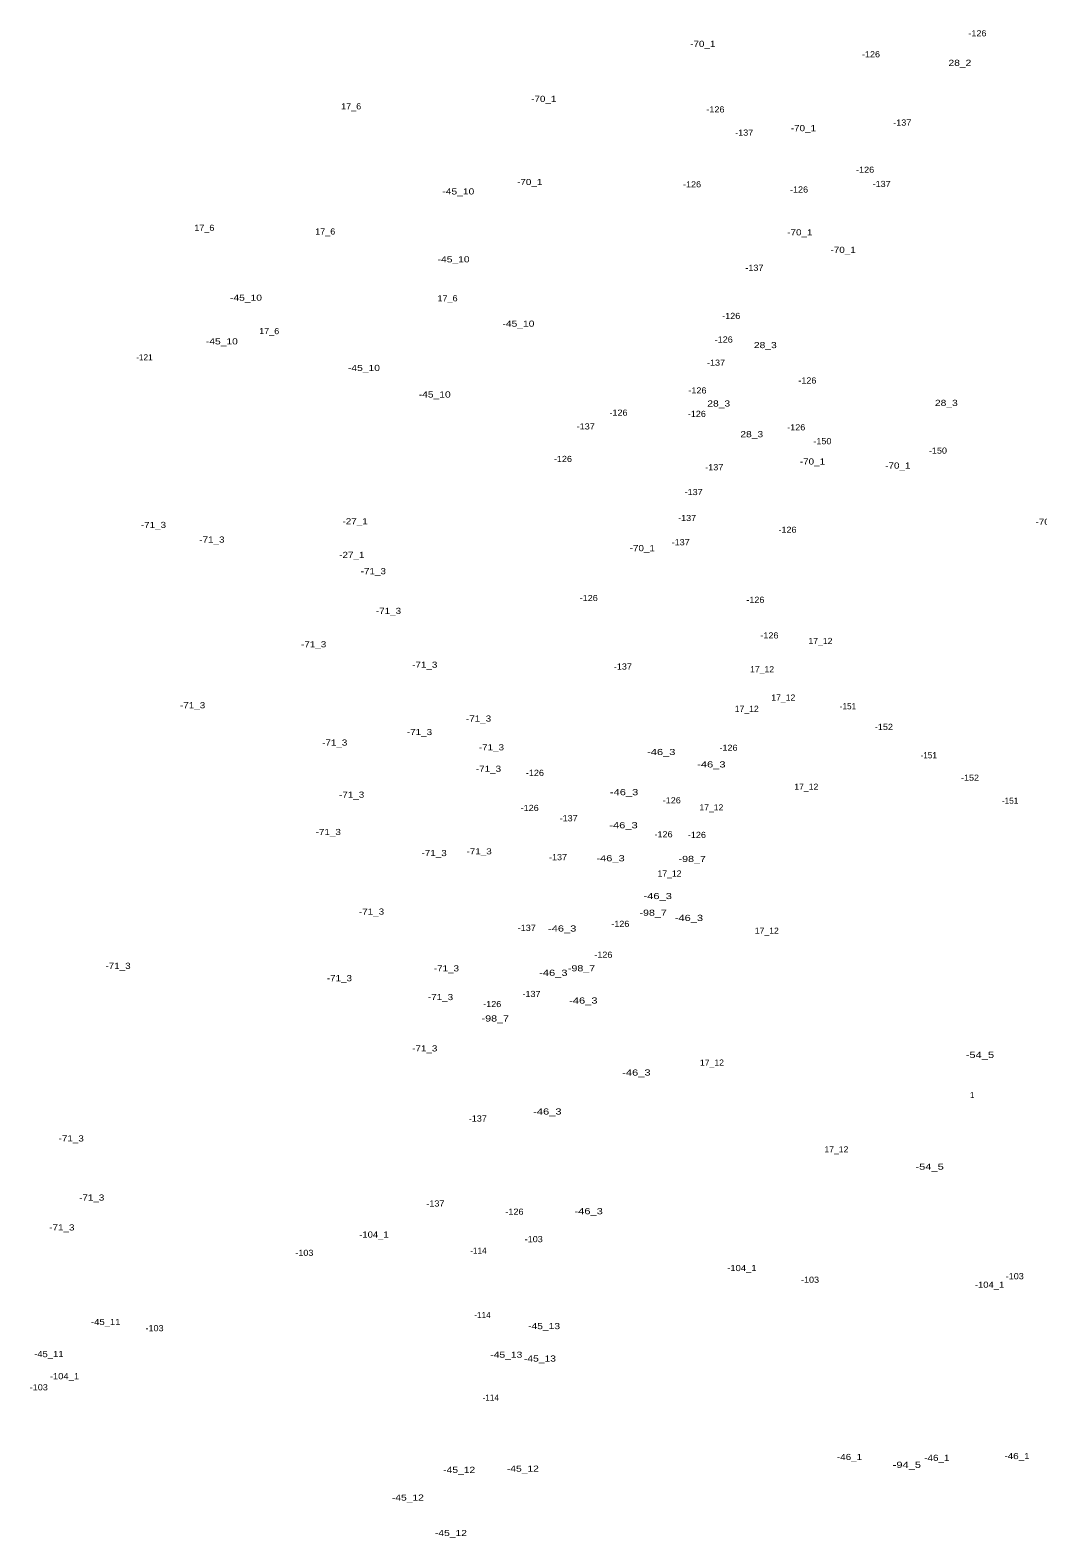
# Model space of a CAD drawing. Extents: x -662996 to -659766, y -998554 to -993949.
# Drawn here: x -662156 to -661500, y -998253 to -997272 of the extents above; entities that cross this region are included whole.
import ezdxf
from ezdxf.enums import TextEntityAlignment as Align

# ---------------------------------------------------------------- set-up
doc = ezdxf.new("R2010")
doc.units = 0
doc.header["$LTSCALE"] = 1.6
doc.layers.add('24', color=7, linetype='Continuous')

msp = doc.modelspace()

# ---------------------------------------------------------------- texts
at = {"layer": '24'}
for s, width, p in [('-126', 1.1, (-661539.28, -997275.58)), ('-70_1', 1.2, (-661718.111, -997282.43)), ('-126', 1.1, (-661608.59, -997289.21)), ('28_2', 1.25, (-661550.68, -997294.78)), ('-70_1', 1.2, (-661821.691, -997318.24)), ('17_6', 1.1, (-661947.12, -997323.09)), ('-126', 1.1, (-661709.89, -997325.1)), ('-70_1', 1.2, (-661652.611, -997337.28)), ('-137', 1.1, (-661588.22, -997333.66)), ('-137', 1.1, (-661691.14, -997340.19)), ('-126', 1.1, (-661612.4, -997364.34)), ('-45_10', 1.25, (-661877.35, -997378.47)), ('-70_1', 1.2, (-661830.831, -997372.33)), ('-126', 1.1, (-661725.12, -997373.86)), ('-126', 1.1, (-661655.43, -997377.21)), ('-137', 1.1, (-661601.66, -997373.61)), ('17_6', 1.1, (-662042.74, -997402.14)), ('17_6', 1.1, (-661964.01, -997404.53)), ('-70_1', 1.2, (-661654.89, -997405.09)), ('-70_1', 1.2, (-661626.711, -997416.52)), ('-45_10', 1.25, (-661880.419, -997422.65)), ('-137', 1.1, (-661684.53, -997428.17)), ('-45_10', 1.25, (-662015.6, -997447.62)), ('17_6', 1.1, (-661884.341, -997448.02)), ('-45_10', 1.25, (-661838.179, -997464.52)), ('-126', 1.1, (-661699.6, -997459.49)), ('-45_10', 1.25, (-662031.34, -997476.05)), ('17_6', 1.1, (-662000.49, -997469.36)), ('-126', 1.1, (-661704.48, -997474.83)), ('28_3', 1.25, (-661677.4, -997478.46)), ('-45_10', 1.25, (-661938.79, -997493.33)), ('-137', 1.1, (-661709.5, -997489.91)), ('-126', 1.1, (-661650.02, -997501.5)), ('-45_10', 1.25, (-661892.709, -997510.62)), ('-126', 1.1, (-661721.61, -997507.98)), ('-126', 1.1, (-661773.02, -997522.45)), ('-126', 1.1, (-661721.99, -997523.22)), ('28_3', 1.25, (-661707.74, -997516.49)), ('28_3', 1.25, (-661559.51, -997516.1)), ('-137', 1.1, (-661794.36, -997531.4)), ('-126', 1.1, (-661657.25, -997531.98)), ('28_3', 1.25, (-661686.23, -997536.46)), ('-150', 1.1, (-661640.24, -997541)), ('-126', 1.1, (-661809.2, -997552.55)), ('-70_1', 1.2, (-661646.701, -997554.22)), ('-150', 1.1, (-661564.981, -997547.14)), ('-137', 1.1, (-661710.65, -997557.96)), ('-70_1', 1.2, (-661591.101, -997556.88)), ('-137', 1.1, (-661724.09, -997574.1)), ('-27_1', 1.2, (-661944.57, -997593.13)), ('-137', 1.1, (-661728.31, -997591)), ('-70_1', 1.2, (-661493.231, -997593.46)), ('-71_3', 1.2, (-662075.88, -997595.52)), ('-126', 1.1, (-661662.97, -997598.64)), ('-71_3', 1.2, (-662037.8, -997605.04)), ('-70_1', 1.2, (-661757.52, -997610.6)), ('-137', 1.1, (-661732.53, -997606.75)), ('-27_1', 1.2, (-661946.68, -997615.02)), ('-71_3', 1.2, (-661932.7, -997625.59)), ('-126', 1.1, (-661792.41, -997643.08)), ('-71_3', 1.2, (-661922.8, -997651.46)), ('-126', 1.1, (-661683.87, -997644.23)), ('-126', 1.1, (-661674.73, -997667.41)), ('17_12', 1.05, (-661641.49, -997671.01)), ('-71_3', 1.2, (-661971.54, -997673.17)), ('-71_3', 1.2, (-661899.19, -997686.48)), ('-137', 1.1, (-661770.17, -997687.64)), ('17_12', 1.05, (-661679.5, -997689.42)), ('17_12', 1.05, (-661665.68, -997707.86)), ('-71_3', 1.2, (-662050.37, -997712.85)), ('-71_3', 1.2, (-661864.15, -997721.53)), ('17_12', 1.05, (-661689.49, -997715.16)), ('-71_3', 1.2, (-661902.61, -997730.29)), ('-152', 1.1, (-661600.16, -997726.95)), ('-71_3', 1.2, (-661957.83, -997737.15)), ('-71_3', 1.2, (-661855.77, -997740.2)), ('-126', 1.1, (-661701.39, -997740.52)), ('-46_3', 1.35, (-661745.18, -997743.28)), ('-46_3', 1.35, (-661712.54, -997751.35)), ('-71_3', 1.2, (-661857.68, -997754.18)), ('-126', 1.1, (-661827.44, -997756.83)), ('-152', 1.1, (-661544.101, -997759.99)), ('-71_3', 1.2, (-661946.79, -997771.05)), ('-46_3', 1.35, (-661769.37, -997769.4)), ('17_12', 1.05, (-661650.7, -997765.89)), ('-126', 1.1, (-661830.87, -997779.69)), ('-126', 1.1, (-661738.33, -997774.74)), ('17_12', 1.05, (-661712.53, -997779.31)), ('-137', 1.1, (-661805.5, -997786.37)), ('-71_3', 1.2, (-661962.02, -997795.33)), ('-46_3', 1.35, (-661769.76, -997790.92)), ('-126', 1.1, (-661743.66, -997796.83)), ('-126', 1.1, (-661721.95, -997797.22)), ('-71_3', 1.2, (-661893.09, -997809.04)), ('-71_3', 1.2, (-661863.77, -997807.9)), ('-137', 1.1, (-661812.41, -997811.72)), ('-46_3', 1.35, (-661778.21, -997812.43)), ('-98_7', 1.3, (-661724.99, -997812.88)), ('17_12', 1.05, (-661739.79, -997822.34)), ('-46_3', 1.35, (-661747.48, -997837.02)), ('-71_3', 1.2, (-661933.84, -997847.14)), ('-98_7', 1.3, (-661750.451, -997847.87)), ('-137', 1.1, (-661832.76, -997857.71)), ('-46_3', 1.35, (-661809.7, -997858.14)), ('-126', 1.1, (-661771.84, -997855.12)), ('-46_3', 1.35, (-661727.17, -997851.24)), ('17_12', 1.05, (-661676.43, -997859.57)), ('-126', 1.1, (-661782.88, -997875.21)), ('-71_3', 1.2, (-662098.96, -997882.45)), ('-71_3', 1.2, (-661885.1, -997884.09)), ('-46_3', 1.35, (-661815.46, -997886.96)), ('-98_7', 1.3, (-661797.091, -997884.03)), ('-71_3', 1.2, (-661954.79, -997890.45)), ('-71_3', 1.2, (-661888.9, -997902.76)), ('-126', 1.1, (-661855.24, -997907.31)), ('-137', 1.1, (-661829.69, -997900.74)), ('-46_3', 1.35, (-661795.91, -997905.02)), ('-98_7', 1.3, (-661853.25, -997916.69)), ('-71_3', 1.2, (-661899.19, -997936.16)), ('17_12', 1.05, (-661712.15, -997945.41)), ('-54_5', 1.35, (-661537.64, -997940.39)), ('-46_3', 1.35, (-661761.35, -997951.89)), ('-137', 1.1, (-661864.64, -997981.79)), ('-46_3', 1.35, (-661819.33, -997977.24)), ('-71_3', 1.2, (-662129.43, -997994.76)), ('17_12', 1.05, (-661631.12, -998001.88)), ('-54_5', 1.35, (-661570.4, -998013.15)), ('-71_3', 1.2, (-662116.1, -998033.24)), ('-137', 1.1, (-661892.29, -998037.11)), ('-126', 1.1, (-661840.77, -998042.45)), ('-46_3', 1.35, (-661792.45, -998042.1)), ('-71_3', 1.2, (-662135.52, -998052.67)), ('-104_1', 1.15, (-661932.29, -998057.33)), ('-103', 1.1, (-661828.231, -998060.3)), ('-103', 1.1, (-661977.601, -998069.24)), ('-104_1', 1.15, (-661692.669, -998079.11)), ('-103', 1.1, (-661514.961, -998084.41)), ('-103', 1.1, (-661648.28, -998086.74)), ('-104_1', 1.15, (-661531.37, -998090)), ('-45_11', 1.15, (-662106.939, -998114.19)), ('-103', 1.1, (-662075.16, -998118.23)), ('-45_13', 1.25, (-661821.49, -998116.89)), ('-45_11', 1.15, (-662144, -998135.12)), ('-45_13', 1.25, (-661846.059, -998135.52)), ('-45_13', 1.25, (-661824.169, -998138.01)), ('-104_1', 1.15, (-662133.819, -998149.48)), ('-103', 1.1, (-662150.561, -998156.73)), ('-46_1', 1.2, (-661622.54, -998202.06)), ('-46_1', 1.2, (-661565.7, -998202.63)), ('-46_1', 1.2, (-661513.48, -998201.48)), ('-45_12', 1.25, (-661876.77, -998210.44)), ('-45_12', 1.25, (-661835.299, -998209.67)), ('-94_5', 1.35, (-661585.24, -998207.17)), ('-45_12', 1.25, (-661910.179, -998228.5)), ('-45_12', 1.25, (-661882.15, -998251.55))]:
    msp.add_text(s, height=4, dxfattribs=dict(at, width=width)).set_placement(p, align=Align.CENTER)
for s, p in [('-121', (-662081.74, -997486.41)), ('-151', (-661623.591, -997713.5)), ('-151', (-661570.981, -997745.39)), ('-151', (-661517.981, -997774.97)), ('1', (-661542.622, -997966.48)), ('-114', (-661864.24, -998067.81)), ('-114', (-661861.57, -998109.71)), ('-114', (-661856.24, -998163.43))]:
    msp.add_text(s, height=4, dxfattribs=at).set_placement(p, align=Align.CENTER)

doc.saveas('drawing.dxf')
